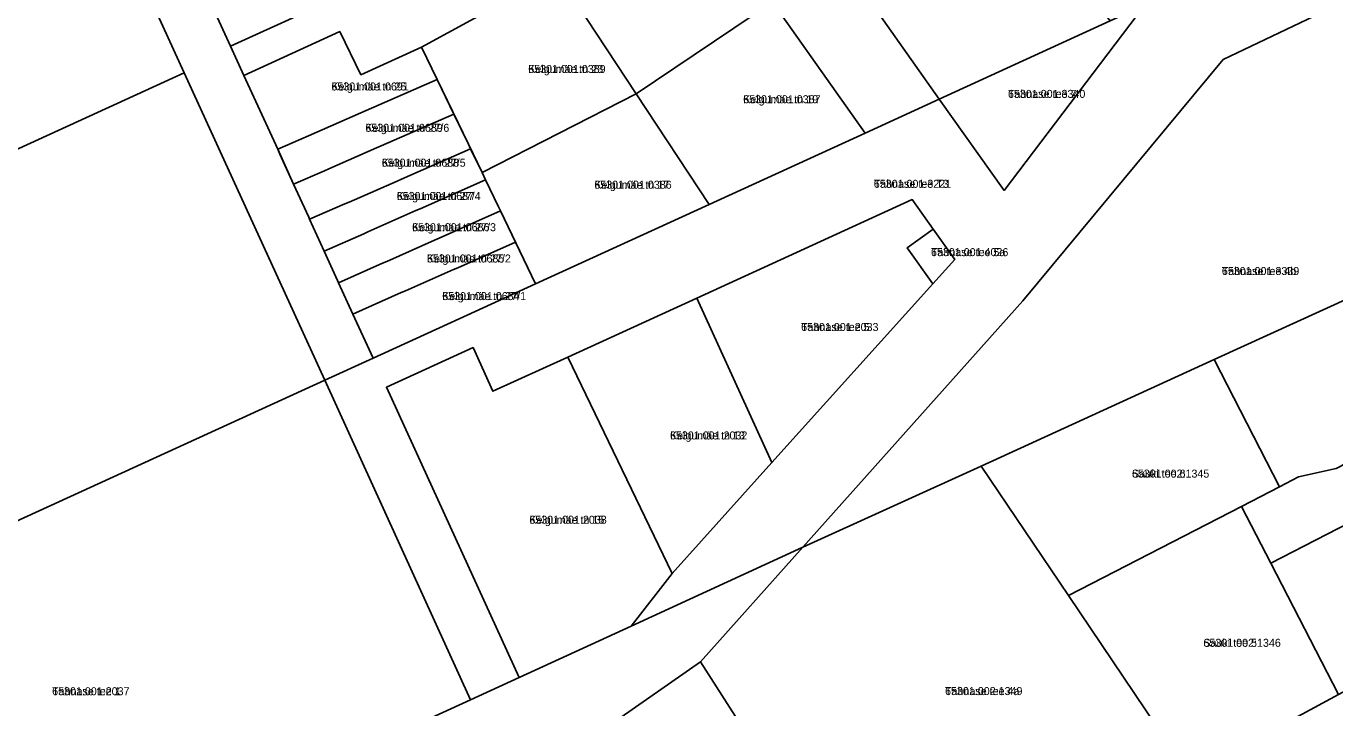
# Model space of a CAD drawing. Extents: x 543236 to 563717, y 6566033 to 6588992.
# Drawn here: x 546441.8 to 546687, y 6585121.5 to 6585249.2 of the extents above; entities that cross this region are included whole.
import ezdxf

# ---------------------------------------------------------------- set-up
doc = ezdxf.new("R2010")
doc.units = 0
for name, color, linetype in [('L_AADRESS', 7, 'Continuous'), ('PIIR', 7, 'Continuous'), ('TUNNUS', 7, 'Continuous')]:
    doc.layers.add(name, color=color, linetype=linetype)

msp = doc.modelspace()

# ---------------------------------------------------------------- linework, layer by layer
at = {"layer": 'PIIR'}
for points in [[(546318.59, 6585170.56), (546277.41, 6585232.67), (546295.29, 6585243.78), (546353.02, 6585262.32), (546356.16, 6585263.99), (546367.4, 6585272.86), (546373.91, 6585264.71), (546390.11, 6585277.48), (546374.24, 6585297.35), (546418.67, 6585332.37), (546444.07, 6585300.18), (546471.39, 6585240.4)], [(546541.2, 6585259.07), (546565.55, 6585276.33), (546581.62, 6585253.67), (546556.08, 6585236.52)], [(546600.86, 6585252.46), (546627.72, 6585271.49), (546644.94, 6585250.18), (546612.87, 6585235.5)], [(546476.23, 6585253.86), (546487.02, 6585258.64), (546487.83, 6585259), (546496.73, 6585262.94), (546497.58, 6585263.32), (546502.76, 6585265.61), (546507.3, 6585257.82), (546480.1, 6585245.39)], [(546515.89, 6585245.26), (546541.2, 6585259.07), (546556.08, 6585236.52), (546527.22, 6585221.73), (546524.65, 6585227.04), (546518.8, 6585239.19)], [(546556.08, 6585236.52), (546581.62, 6585253.67), (546599, 6585229.14), (546569.76, 6585215.78)], [(546666.1, 6585242.92), (546688.38, 6585253.53), (546709.5, 6585207.29), (546705.24, 6585205.35), (546664.42, 6585186.71), (546620.75, 6585166.75), (546587.35, 6585151.57), (546628.58, 6585197.73)], [(546644.94, 6585250.18), (546651.34, 6585253.06), (546625.03, 6585218.39), (546612.87, 6585235.5)], [(546482.6, 6585239.93), (546500.55, 6585248.14), (546504.5, 6585240.05), (546515.89, 6585245.26), (546518.8, 6585239.19), (546504.47, 6585232.92), (546494.7, 6585228.64), (546488.92, 6585226.1)], [(546354, 6585117.16), (546318.59, 6585170.56), (546471.39, 6585240.4), (546497.73, 6585182.86)], [(546488.92, 6585226.1), (546494.7, 6585228.64), (546504.47, 6585232.92), (546518.8, 6585239.19), (546521.92, 6585232.7), (546508.28, 6585226.73), (546507.45, 6585226.36), (546498.48, 6585222.43), (546497.66, 6585222.07), (546491.91, 6585219.56)], [(546527.22, 6585221.73), (546556.08, 6585236.52), (546569.76, 6585215.78), (546537.25, 6585200.92), (546530.67, 6585214.57), (546530.3, 6585215.33), (546527.87, 6585220.41)], [(546491.91, 6585219.56), (546497.66, 6585222.07), (546498.48, 6585222.43), (546507.45, 6585226.36), (546508.28, 6585226.73), (546521.92, 6585232.7), (546524.65, 6585227.04), (546525.06, 6585226.19), (546512.1, 6585220.52), (546511.28, 6585220.16), (546502.31, 6585216.23), (546501.48, 6585215.86), (546494.91, 6585212.99), (546494.74, 6585213.37)], [(546494.91, 6585212.99), (546501.48, 6585215.86), (546502.31, 6585216.23), (546511.28, 6585220.16), (546512.1, 6585220.52), (546525.06, 6585226.19), (546527.22, 6585221.73), (546527.87, 6585220.41), (546515.62, 6585214.97), (546514.8, 6585214.61), (546505.84, 6585210.64), (546505.03, 6585210.28), (546497.64, 6585207.01)], [(546760.87, 6585223.22), (546769.82, 6585217.58), (546756.69, 6585190.63), (546719.18, 6585171.31), (546675.05, 6585148.56), (546669.55, 6585159.23), (546676.68, 6585162.9), (546680.22, 6585164.73), (546687.26, 6585166.33), (546717.34, 6585181.84), (546748.53, 6585197.9)], [(546497.64, 6585207.01), (546505.03, 6585210.28), (546505.84, 6585210.64), (546514.8, 6585214.61), (546515.62, 6585214.97), (546527.87, 6585220.41), (546530.3, 6585215.33), (546530.67, 6585214.57), (546519.15, 6585209.45), (546518.32, 6585209.09), (546509.37, 6585205.11), (546508.55, 6585204.75), (546500.34, 6585201.11), (546500.14, 6585201.55)], [(546567.47, 6585198.24), (546607.83, 6585216.69), (546611.76, 6585211.12), (546606.89, 6585207.65), (546611.67, 6585200.89), (546581.55, 6585167.44)], [(546500.34, 6585201.11), (546508.55, 6585204.75), (546509.37, 6585205.11), (546518.32, 6585209.09), (546519.15, 6585209.45), (546530.67, 6585214.57), (546533.49, 6585208.72), (546522.67, 6585203.93), (546521.85, 6585203.57), (546512.89, 6585199.61), (546512.07, 6585199.25), (546503.02, 6585195.24)], [(546606.89, 6585207.65), (546611.76, 6585211.12), (546615.8, 6585205.45), (546611.67, 6585200.89)], [(546503.02, 6585195.24), (546512.07, 6585199.25), (546512.89, 6585199.61), (546521.85, 6585203.57), (546522.67, 6585203.93), (546533.49, 6585208.72), (546537.25, 6585200.92), (546522.95, 6585194.38), (546506.79, 6585187)], [(546705.24, 6585205.35), (546717.34, 6585181.84), (546687.26, 6585166.33), (546680.22, 6585164.73), (546676.68, 6585162.9), (546664.42, 6585186.71)], [(546543.32, 6585187.2), (546567.47, 6585198.24), (546581.55, 6585167.44), (546562.87, 6585146.68)], [(546509.29, 6585181.54), (546525.52, 6585188.96), (546529.26, 6585180.77), (546543.32, 6585187.2), (546562.87, 6585146.68), (546555.17, 6585136.77), (546534.14, 6585127.16)], [(546687.71, 6585123.99), (546731.86, 6585147.88), (546768.95, 6585167.96), (546807.3, 6585188.71), (546874.25, 6585137.4), (546849.87, 6585118.09), (546847.76, 6585116.42), (546817.23, 6585092.24), (546798.66, 6585077.53), (546787.67, 6585068.83), (546746.49, 6585036.21), (546741.77, 6585032.47), (546721.93, 6585016.76), (546690.88, 6585062.81), (546659.79, 6585108.88)], [(546664.42, 6585186.71), (546676.68, 6585162.9), (546669.55, 6585159.23), (546637.09, 6585142.5), (546620.75, 6585166.75)], [(546354, 6585117.16), (546497.73, 6585182.86), (546525.05, 6585123.01), (546421.91, 6585075.88), (546419.15, 6585080.98), (546410.56, 6585077.06), (546413.29, 6585071.94), (546397.74, 6585064.84)], [(546719.18, 6585171.31), (546731.86, 6585147.88), (546687.71, 6585123.99), (546675.05, 6585148.56)], [(546620.75, 6585166.75), (546637.09, 6585142.5), (546659.79, 6585108.88), (546615.83, 6585085.08), (546601.84, 6585077.52), (546568.18, 6585130.1), (546587.35, 6585151.57)], [(546669.55, 6585159.23), (546675.05, 6585148.56), (546687.71, 6585123.99), (546659.79, 6585108.88), (546637.09, 6585142.5)], [(546587.35, 6585151.57), (546568.18, 6585130.1), (546533.65, 6585106.05), (546516.3, 6585097.87), (546463.57, 6585073.04), (546407.53, 6585046.64), (546397.74, 6585064.84), (546413.29, 6585071.94), (546421.89, 6585075.87), (546525.05, 6585123.01), (546534.14, 6585127.16), (546555.17, 6585136.77)], [(546568.18, 6585130.1), (546601.84, 6585077.52), (546564.83, 6585057.48), (546533.65, 6585106.05)]]:
    msp.add_lwpolyline(points, close=True, dxfattribs=at)
for points in [[(546476.23, 6585253.86), (546480.1, 6585245.39), (546482.6, 6585239.93), (546488.92, 6585226.1), (546489.33, 6585225.2), (546491.91, 6585219.56), (546494.74, 6585213.37), (546494.91, 6585212.99), (546497.64, 6585207.01), (546500.14, 6585201.55), (546500.34, 6585201.11), (546503.02, 6585195.24), (546506.79, 6585187), (546497.73, 6585182.86), (546471.39, 6585240.4), (546444.07, 6585300.18)], [(546541.2, 6585259.07), (546515.89, 6585245.26), (546504.5, 6585240.05), (546500.55, 6585248.14), (546482.6, 6585239.93), (546480.1, 6585245.39), (546507.3, 6585257.82)], [(546688.38, 6585253.53), (546666.1, 6585242.92), (546628.58, 6585197.73), (546587.35, 6585151.57), (546555.17, 6585136.77), (546562.87, 6585146.68), (546581.55, 6585167.44), (546611.67, 6585200.89), (546615.8, 6585205.45), (546611.76, 6585211.12), (546607.83, 6585216.69), (546567.47, 6585198.24), (546543.32, 6585187.2), (546529.26, 6585180.77), (546525.52, 6585188.96), (546509.29, 6585181.54), (546534.14, 6585127.16), (546525.05, 6585123.01), (546497.73, 6585182.86), (546506.79, 6585187), (546522.95, 6585194.38), (546537.25, 6585200.92), (546569.76, 6585215.78), (546599, 6585229.14), (546612.87, 6585235.5), (546625.03, 6585218.39), (546651.34, 6585253.06)], [(546600.86, 6585252.46), (546612.87, 6585235.5), (546599, 6585229.14), (546581.62, 6585253.67)]]:
    msp.add_lwpolyline(points, dxfattribs=at)

# ---------------------------------------------------------------- texts
at = {"layer": 'L_AADRESS'}
for s, p in [('Kelgumäe tn 23', (546535.87, 6585240.4)), ('Kelgumäe tn 25', (546498.98, 6585237.12)), ('Tähnase tee 7', (546625.77, 6585235.73)), ('Kelgumäe tn 19', (546576.15, 6585234.73)), ('Kelgumäe tn 27/6', (546505.35, 6585229.38)), ('Kelgumäe tn 27/5', (546508.42, 6585222.84)), ('Kelgumäe tn 17', (546548.25, 6585218.72)), ('Tähnase tee T3', (546600.62, 6585218.89)), ('Kelgumäe tn 27/4', (546511.22, 6585216.6)), ('Kelgumäe tn 27/3', (546514.1, 6585210.76)), ('Tähnase tee 5a', (546611.34, 6585206.09)), ('Kelgumäe tn 27/2', (546516.89, 6585204.9)), ('Tähnase tee 4b', (546665.85, 6585202.55)), ('Kelgumäe tn 27/1', (546519.75, 6585197.86)), ('Tähnase tee 5', (546587.01, 6585192.07)), ('Kelgumäe tn 13', (546562.43, 6585171.76)), ('Sauki tee 6', (546649, 6585164.61)), ('Kelgumäe tn 15', (546536.08, 6585155.97)), ('Sauki tee 5', (546662.4, 6585132.92)), ('Tähnase tee 1', (546446.65, 6585123.85)), ('Tähnase tee 4a', (546613.98, 6585123.88))]:
    msp.add_text(s, height=1.5, dxfattribs=at).set_placement(p)
at = {"layer": 'TUNNUS'}
for s, p in [('65301:001:0389', (546535.87, 6585240.4)), ('65301:001:0691', (546498.98, 6585237.12)), ('65301:001:3340', (546625.77, 6585235.73)), ('65301:001:0387', (546576.15, 6585234.73)), ('65301:001:0689', (546505.35, 6585229.38)), ('65301:001:0688', (546508.42, 6585222.84)), ('65301:001:0386', (546548.25, 6585218.72)), ('65301:001:3221', (546600.62, 6585218.89)), ('65301:001:0687', (546511.22, 6585216.6)), ('65301:001:0686', (546514.1, 6585210.76)), ('65301:001:4026', (546611.34, 6585206.09)), ('65301:001:0685', (546516.89, 6585204.9)), ('65301:001:3339', (546665.85, 6585202.55)), ('65301:001:0684', (546519.75, 6585197.86)), ('65301:001:2033', (546587.01, 6585192.07)), ('65301:001:2032', (546562.43, 6585171.76)), ('65301:002:1345', (546649, 6585164.61)), ('65301:001:2038', (546536.08, 6585155.97)), ('65301:002:1346', (546662.4, 6585132.92)), ('65301:001:2037', (546446.65, 6585123.85)), ('65301:002:1349', (546613.98, 6585123.88))]:
    msp.add_text(s, height=1.5, dxfattribs=at).set_placement(p)

doc.saveas('drawing.dxf')
